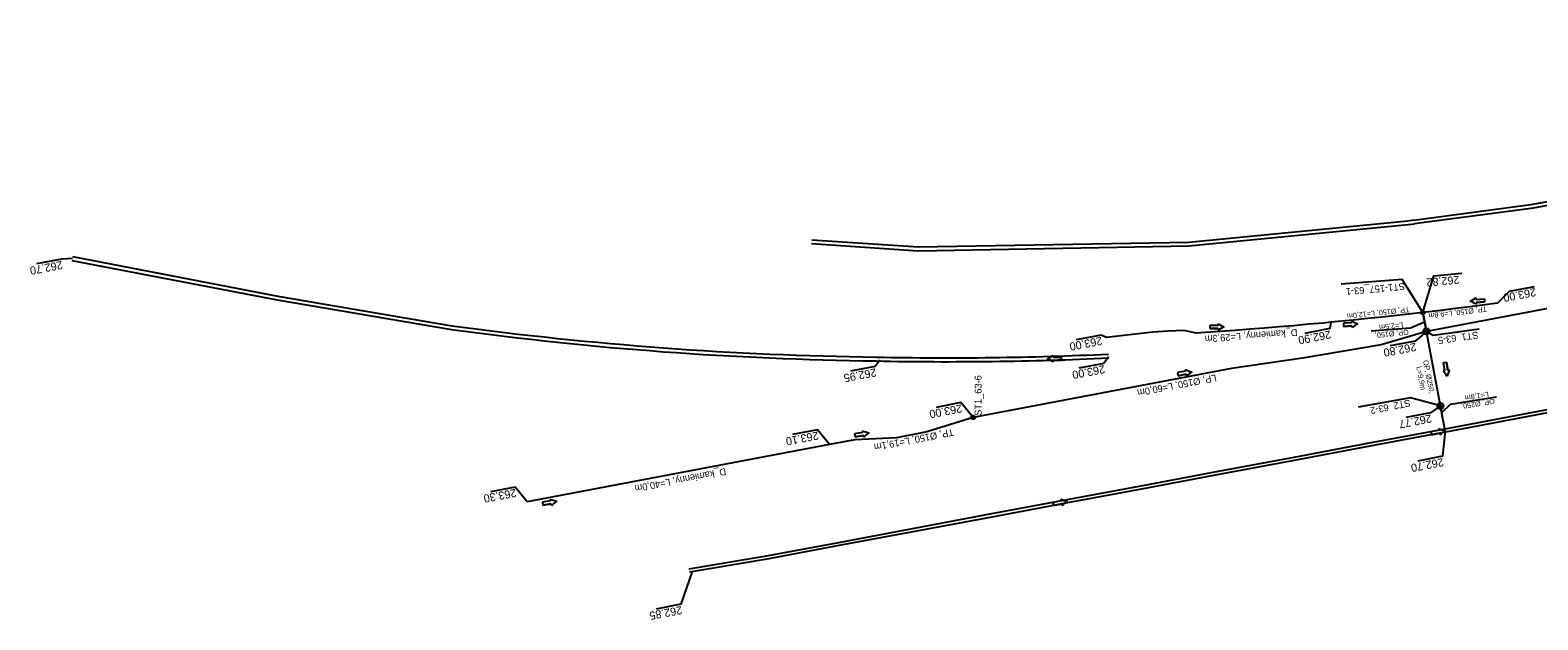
# Model space of a CAD drawing. Extents: x -1 to 65640748, y -22 to 5530284.
# Drawn here: x 6555645.9 to 6555842, y 5528336.8 to 5528413.6 of the extents above; entities that cross this region are included whole.
import ezdxf

# ---------------------------------------------------------------- set-up
doc = ezdxf.new("R2010")
doc.units = 0
for name, color, linetype in [('TOR_PROF-studnie i osadniki', 7, 'Continuous'), ('TOR_PS_ODW-drenaze', 7, 'Continuous'), ('TOR_PS_ODW-drenokolektory', 7, 'Continuous'), ('TOR_PS_ODW-kolektory', 7, 'Continuous'), ('TOR_PS_ODW-studnie PEHD', 7, 'Continuous'), ('TOR_PS_OPIS_O-opisy rurociagow', 7, 'Continuous'), ('TOR_PS_OPIS_O-opisy studni', 7, 'Continuous'), ('TOR_PS_OPIS_T-INFO', 7, 'Continuous'), ('TOR_PS_T-rowy otwarte nieumocnione', 7, 'Continuous'), ('TOR_PS_T-rowy otwarte umocnione', 7, 'Continuous')]:
    doc.layers.add(name, color=color, linetype=linetype)

msp = doc.modelspace()

# ---------------------------------------------------------------- linework, layer by layer
at = {"layer": 'TOR_PROF-studnie i osadniki'}
for centre, radius in [((6555827.04, 5528376.82), 0.25), ((6555827.04, 5528376.82), 0.125), ((6555768.56, 5528363.17), 0.25), ((6555768.56, 5528363.17), 0.125)]:
    msp.add_circle(centre, radius, dxfattribs=at)
at = {"layer": 'TOR_PS_ODW-drenaze'}
msp.add_line((6555749.88, 5528359.64), (6555710.58, 5528352.19), dxfattribs=at)
for points in [[(6555836.74, 5528378.02), (6555835.12, 5528377.8), (6555833.21, 5528377.56), (6555831.31, 5528377.33), (6555829.4, 5528377.09), (6555827.49, 5528376.87), (6555827.04, 5528376.82)], [(6555815.07, 5528375.54), (6555814.12, 5528375.45), (6555812.2, 5528375.28), (6555810.29, 5528375.1), (6555808.37, 5528374.94), (6555806.46, 5528374.78), (6555804.54, 5528374.63), (6555802.62, 5528374.49), (6555800.71, 5528374.35), (6555798.79, 5528374.22), (6555797.58, 5528374.15), (6555795.95, 5528374.49), (6555793.95, 5528374.39), (6555791.95, 5528374.28), (6555785.92, 5528373.56)], [(6555827.04, 5528376.82), (6555825.58, 5528376.65), (6555823.67, 5528376.43), (6555821.76, 5528376.23), (6555819.85, 5528376.02), (6555817.94, 5528375.83), (6555816.03, 5528375.64), (6555815.07, 5528375.54)], [(6555768.56, 5528363.17), (6555762.53, 5528361.27), (6555758.6, 5528360.52), (6555753.18, 5528360.26), (6555749.88, 5528359.64)]]:
    msp.add_lwpolyline(points, dxfattribs=at)
at = {"layer": 'TOR_PS_ODW-drenokolektory'}
for points in [[(6555871.72, 5528382.73), (6555827.51, 5528374.35), (6555827.51, 5528374.35)], [(6555827.51, 5528374.35), (6555821.64, 5528372.6), (6555811.41, 5528370.88), (6555802.18, 5528369.55), (6555768.56, 5528363.17)]]:
    msp.add_lwpolyline(points, dxfattribs=at)
at = {"layer": 'TOR_PS_ODW-kolektory'}
for points in [[(6555829.91, 5528361.65), (6555829.34, 5528364.67), (6555827.51, 5528374.35), (6555827.04, 5528376.82)], [(6555827.04, 5528376.82), (6555827.51, 5528374.35)], [(6555829.91, 5528361.65), (6555829.34, 5528364.67), (6555827.51, 5528374.35)], [(6555829.91, 5528361.65), (6555829.34, 5528364.67), (6555827.51, 5528374.35)], [(6555829.91, 5528361.65), (6555829.34, 5528364.67), (6555827.51, 5528374.35)], [(6555829.67, 5528362.94), (6555829.34, 5528364.67), (6555829.34, 5528364.67)]]:
    msp.add_lwpolyline(points, dxfattribs=at)
at = {"layer": 'TOR_PS_ODW-studnie PEHD'}
for centre, radius in [((6555827.04, 5528376.82), 0.25), ((6555827.04, 5528376.82), 0.112), ((6555827.51, 5528374.35), 0.4), ((6555827.51, 5528374.35), 0.145), ((6555829.34, 5528364.67), 0.4), ((6555829.34, 5528364.67), 0.145), ((6555768.56, 5528363.17), 0.25), ((6555768.56, 5528363.17), 0.112)]:
    msp.add_circle(centre, radius, dxfattribs=at)
at = {"layer": 'TOR_PS_OPIS_O-opisy rurociagow'}
for p, q in [((6555833.96, 5528378.52), (6555835.05, 5528378.6)), ((6555833.96, 5528378.52), (6555835.05, 5528378.6)), ((6555835.07, 5528378.2), (6555833.98, 5528378.12)), ((6555833.98, 5528378.12), (6555835.07, 5528378.2)), ((6555835.05, 5528378.6), (6555835.07, 5528378.2)), ((6555835.05, 5528378.6), (6555835.07, 5528378.2)), ((6555817.81, 5528375.49), (6555816.72, 5528375.41)), ((6555817.81, 5528375.49), (6555816.72, 5528375.41)), ((6555800.44, 5528375.14), (6555799.35, 5528375.12)), ((6555800.44, 5528375.14), (6555799.35, 5528375.12)), ((6555799.35, 5528375.12), (6555799.35, 5528374.72)), ((6555799.35, 5528375.12), (6555799.35, 5528374.72)), ((6555799.35, 5528374.72), (6555800.45, 5528374.74)), ((6555800.45, 5528374.74), (6555799.35, 5528374.72)), ((6555816.72, 5528375.41), (6555816.75, 5528375.01)), ((6555816.72, 5528375.41), (6555816.75, 5528375.01)), ((6555816.75, 5528375.01), (6555817.84, 5528375.09)), ((6555817.84, 5528375.09), (6555816.75, 5528375.01)), ((6555780.07, 5528371.02), (6555778.98, 5528371.01)), ((6555778.98, 5528371.01), (6555780.07, 5528371.02)), ((6555778.98, 5528370.61), (6555780.07, 5528370.62)), ((6555778.98, 5528370.61), (6555780.07, 5528370.62)), ((6555780.07, 5528370.62), (6555780.07, 5528371.02)), ((6555780.07, 5528370.62), (6555780.07, 5528371.02)), ((6555829.74, 5528370.32), (6555830.13, 5528370.37)), ((6555829.74, 5528370.32), (6555830.13, 5528370.37)), ((6555829.9, 5528369.24), (6555829.74, 5528370.32)), ((6555829.9, 5528369.24), (6555829.74, 5528370.32)), ((6555830.13, 5528370.37), (6555830.29, 5528369.29)), ((6555830.29, 5528369.29), (6555830.13, 5528370.37)), ((6555796.22, 5528369.17), (6555795.14, 5528368.99)), ((6555796.22, 5528369.17), (6555795.14, 5528368.99)), ((6555795.14, 5528368.99), (6555795.21, 5528368.59)), ((6555795.14, 5528368.99), (6555795.21, 5528368.59)), ((6555795.21, 5528368.59), (6555796.28, 5528368.78)), ((6555796.28, 5528368.78), (6555795.21, 5528368.59)), ((6555754.23, 5528361.21), (6555753.15, 5528361.03)), ((6555754.23, 5528361.21), (6555753.15, 5528361.03)), ((6555753.15, 5528361.03), (6555753.22, 5528360.63)), ((6555753.15, 5528361.03), (6555753.22, 5528360.63)), ((6555753.22, 5528360.63), (6555754.29, 5528360.82)), ((6555754.29, 5528360.82), (6555753.22, 5528360.63)), ((6555829.17, 5528361.51), (6555828.09, 5528361.31)), ((6555829.17, 5528361.51), (6555828.09, 5528361.31)), ((6555828.09, 5528361.31), (6555828.17, 5528360.91)), ((6555828.09, 5528361.31), (6555828.17, 5528360.91)), ((6555828.17, 5528360.91), (6555829.24, 5528361.12)), ((6555829.24, 5528361.12), (6555828.17, 5528360.91)), ((6555713.62, 5528352.32), (6555712.55, 5528352.14)), ((6555713.62, 5528352.32), (6555712.55, 5528352.14)), ((6555712.55, 5528352.14), (6555712.61, 5528351.74)), ((6555712.55, 5528352.14), (6555712.61, 5528351.74)), ((6555780.02, 5528352.3), (6555778.95, 5528352.1)), ((6555780.02, 5528352.3), (6555778.95, 5528352.1)), ((6555778.95, 5528352.1), (6555779.02, 5528351.71)), ((6555778.95, 5528352.1), (6555779.02, 5528351.71)), ((6555712.61, 5528351.74), (6555713.69, 5528351.93)), ((6555713.69, 5528351.93), (6555712.61, 5528351.74)), ((6555779.02, 5528351.71), (6555780.1, 5528351.91)), ((6555780.1, 5528351.91), (6555779.02, 5528351.71))]:
    msp.add_line(p, q, dxfattribs=at)
for points in [[(6555833.95, 5528378.75), (6555833.95, 5528378.75)], [(6555834.01, 5528377.9), (6555834.01, 5528377.9)], [(6555817.78, 5528375.72), (6555817.78, 5528375.72)], [(6555800.42, 5528375.37), (6555800.42, 5528375.37)], [(6555800.44, 5528374.52), (6555800.44, 5528374.52)], [(6555817.85, 5528374.87), (6555817.85, 5528374.87)], [(6555778.98, 5528371.23), (6555778.98, 5528371.23)], [(6555778.99, 5528370.38), (6555778.99, 5528370.38)], [(6555796.17, 5528369.39), (6555796.17, 5528369.39)], [(6555796.31, 5528368.56), (6555796.31, 5528368.56)], [(6555829.67, 5528369.21), (6555829.67, 5528369.21)], [(6555830.51, 5528369.34), (6555830.51, 5528369.34)], [(6555754.18, 5528361.43), (6555754.18, 5528361.43)], [(6555754.32, 5528360.6), (6555754.32, 5528360.6)], [(6555829.12, 5528361.73), (6555829.12, 5528361.73)], [(6555829.27, 5528360.89), (6555829.27, 5528360.89)], [(6555713.57, 5528352.54), (6555713.57, 5528352.54)], [(6555779.97, 5528352.52), (6555779.97, 5528352.52)], [(6555713.72, 5528351.71), (6555713.72, 5528351.71)], [(6555780.13, 5528351.68), (6555780.13, 5528351.68)]]:
    msp.add_lwpolyline(points, dxfattribs=at)
for centre, radius, start, end in [((6555830.95, 5528382.64), 4.92, 297.3085, 307.6904), ((6555830.95, 5528382.64), 4.92, 297.3085, 307.6904), ((6555831.57, 5528373.63), 4.92, 60.2707, 70.6525), ((6555831.57, 5528373.63), 4.92, 60.2707, 70.6525), ((6555833.51, 5528378.62), 0.458, 347.1146, 15.5758), ((6555833.51, 5528378.62), 0.458, 347.1146, 15.5758), ((6555833.56, 5528377.96), 0.458, 352.3852, 20.8465), ((6555833.56, 5528377.96), 0.458, 352.3852, 20.8465), ((6555820.2, 5528380), 4.92, 240.5204, 250.9022), ((6555818.24, 5528375.66), 0.458, 172.635, 201.0962), ((6555820.2, 5528380), 4.92, 240.5204, 250.9022), ((6555818.24, 5528375.66), 0.458, 172.635, 201.0962), ((6555800.87, 5528375.29), 0.458, 169.7553, 198.2165), ((6555800.87, 5528375.29), 0.458, 169.7553, 198.2165), ((6555803.05, 5528379.52), 4.92, 237.6407, 248.0225), ((6555803.05, 5528379.52), 4.92, 237.6407, 248.0225), ((6555800.89, 5528374.62), 0.458, 164.4846, 192.9458), ((6555800.89, 5528374.62), 0.458, 164.4846, 192.9458), ((6555803.27, 5528370.49), 4.92, 114.6786, 125.0604), ((6555803.27, 5528370.49), 4.92, 114.6786, 125.0604), ((6555818.29, 5528374.99), 0.458, 167.3643, 195.8256), ((6555818.29, 5528374.99), 0.458, 167.3643, 195.8256), ((6555820.87, 5528370.99), 4.92, 117.5583, 127.9401), ((6555820.87, 5528370.99), 4.92, 117.5583, 127.9401), ((6555776.21, 5528375.29), 4.92, 293.986, 304.3678), ((6555776.21, 5528375.29), 4.92, 293.986, 304.3678), ((6555776.31, 5528366.26), 4.92, 56.9481, 67.3299), ((6555776.31, 5528366.26), 4.92, 56.9481, 67.3299), ((6555778.54, 5528371.14), 0.458, 343.792, 12.2532), ((6555778.54, 5528371.14), 0.458, 343.792, 12.2532), ((6555778.55, 5528370.47), 0.458, 349.0626, 17.5239), ((6555778.55, 5528370.47), 0.458, 349.0626, 17.5239), ((6555798.16, 5528373.89), 4.92, 246.1449, 256.5268), ((6555796.62, 5528369.38), 0.458, 178.2595, 206.7208), ((6555798.16, 5528373.89), 4.92, 246.1449, 256.5268), ((6555796.62, 5528369.38), 0.458, 178.2595, 206.7208), ((6555796.74, 5528368.72), 0.458, 172.9889, 201.4501), ((6555796.74, 5528368.72), 0.458, 172.9889, 201.4501), ((6555799.7, 5528364.99), 4.92, 123.1828, 133.5647), ((6555799.7, 5528364.99), 4.92, 123.1828, 133.5647), ((6555829.83, 5528368.78), 0.458, 81.4934, 109.9546), ((6555829.83, 5528368.78), 0.458, 81.4934, 109.9546), ((6555826.02, 5528365.92), 4.92, 31.6874, 42.0692), ((6555826.02, 5528365.92), 4.92, 31.6874, 42.0692), ((6555834.96, 5528367.23), 4.92, 154.6495, 165.0313), ((6555834.96, 5528367.23), 4.92, 154.6495, 165.0313), ((6555830.49, 5528368.88), 0.458, 86.764, 115.2253), ((6555830.49, 5528368.88), 0.458, 86.764, 115.2253), ((6555756.17, 5528365.93), 4.92, 246.1449, 256.5268), ((6555754.63, 5528361.42), 0.458, 178.2595, 206.7208), ((6555756.17, 5528365.93), 4.92, 246.1449, 256.5268), ((6555754.63, 5528361.42), 0.458, 178.2595, 206.7208), ((6555754.75, 5528360.76), 0.458, 172.9889, 201.4501), ((6555754.75, 5528360.76), 0.458, 172.9889, 201.4501), ((6555757.71, 5528357.03), 4.92, 123.1828, 133.5647), ((6555757.71, 5528357.03), 4.92, 123.1828, 133.5647), ((6555831.04, 5528366.25), 4.92, 246.9461, 257.3279), ((6555829.57, 5528361.72), 0.458, 179.0606, 207.5219), ((6555831.04, 5528366.25), 4.92, 246.9461, 257.3279), ((6555829.57, 5528361.72), 0.458, 179.0606, 207.5219), ((6555829.7, 5528361.07), 0.458, 173.79, 202.2512), ((6555829.7, 5528361.07), 0.458, 173.79, 202.2512), ((6555832.71, 5528357.38), 4.92, 123.9839, 134.3658), ((6555832.71, 5528357.38), 4.92, 123.9839, 134.3658), ((6555715.56, 5528357.04), 4.92, 246.1449, 256.5268), ((6555714.03, 5528352.53), 0.458, 178.2595, 206.7208), ((6555715.56, 5528357.04), 4.92, 246.1449, 256.5268), ((6555714.03, 5528352.53), 0.458, 178.2595, 206.7208), ((6555717.11, 5528348.14), 4.92, 123.1828, 133.5647), ((6555717.11, 5528348.14), 4.92, 123.1828, 133.5647), ((6555781.9, 5528357.04), 4.92, 246.9045, 257.2864), ((6555780.43, 5528352.51), 0.458, 179.0191, 207.4803), ((6555781.9, 5528357.04), 4.92, 246.9045, 257.2864), ((6555780.43, 5528352.51), 0.458, 179.0191, 207.4803), ((6555783.57, 5528348.17), 4.92, 123.9424, 134.3242), ((6555783.57, 5528348.17), 4.92, 123.9424, 134.3242), ((6555714.14, 5528351.87), 0.458, 172.9889, 201.4501), ((6555714.14, 5528351.87), 0.458, 172.9889, 201.4501), ((6555780.55, 5528351.86), 0.458, 173.7484, 202.2097), ((6555780.55, 5528351.86), 0.458, 173.7484, 202.2097)]:
    msp.add_arc(centre, radius, start, end, dxfattribs=at)
at = {"layer": 'TOR_PS_OPIS_T-INFO'}
for points in [[(6555651.43, 5528383.83), (6555650, 5528383.76), (6555646.77, 5528383.14)], [(6555827.04, 5528376.82), (6555828.49, 5528381.57), (6555832.14, 5528381.93)], [(6555827.04, 5528376.82), (6555824.38, 5528381.1), (6555816.44, 5528380.49)], [(6555836.74, 5528378.02), (6555838.32, 5528379.61), (6555841.56, 5528380.21)], [(6555815.07, 5528375.54), (6555814.95, 5528374.72), (6555811.72, 5528374.09)], [(6555827.27, 5528375.58), (6555825.43, 5528374.79), (6555820.31, 5528374.39)], [(6555785.92, 5528373.56), (6555785.21, 5528373.89), (6555781.97, 5528373.26)], [(6555827.51, 5528374.35), (6555826.04, 5528373.1), (6555822.81, 5528372.48)], [(6555827.51, 5528374.35), (6555828.41, 5528373.85), (6555834.39, 5528374.7)], [(6555756.43, 5528370.62), (6555755.83, 5528369.79), (6555752.6, 5528369.17)], [(6555786.16, 5528371.03), (6555785.56, 5528370.2), (6555782.32, 5528369.58)], [(6555829.34, 5528364.67), (6555825.44, 5528365.7), (6555818.64, 5528364.49)], [(6555829.5, 5528363.8), (6555830.66, 5528364.91), (6555836.63, 5528365.86)], [(6555768.56, 5528363.17), (6555766.98, 5528365.09), (6555763.75, 5528364.47)], [(6555829.34, 5528364.67), (6555828.05, 5528363.78), (6555824.82, 5528363.16)], [(6555749.88, 5528359.64), (6555748.31, 5528361.55), (6555745.08, 5528360.93)], [(6555829.96, 5528361.46), (6555829.61, 5528358.11), (6555826.38, 5528357.48)], [(6555710.58, 5528352.19), (6555709.01, 5528354.1), (6555705.78, 5528353.48)], [(6555732.01, 5528343.1), (6555730.57, 5528338.86), (6555727.33, 5528338.23)]]:
    msp.add_lwpolyline(points, dxfattribs=at)
at = {"layer": 'TOR_PS_T-rowy otwarte nieumocnione'}
for points in [[(6555825.88, 5528388.85), (6555841.38, 5528390.92), (6555883.85, 5528398.71), (6555924.19, 5528406.04), (6555964.88, 5528413.56)], [(6555825.94, 5528388.38), (6555841.45, 5528390.45), (6555883.94, 5528398.24), (6555924.27, 5528405.57), (6555964.49, 5528413.01), (6555964.97, 5528413.1)], [(6555761.43, 5528385.35), (6555796.6, 5528385.99), (6555825.1, 5528388.76), (6555825.88, 5528388.86)], [(6555761.44, 5528384.85), (6555796.63, 5528385.49), (6555825.15, 5528388.26), (6555825.95, 5528388.37)], [(6555747.55, 5528385.79), (6555761.42, 5528384.85)], [(6555747.57, 5528386.29), (6555761.46, 5528385.35)]]:
    msp.add_lwpolyline(points, dxfattribs=at)
at = {"layer": 'TOR_PS_T-rowy otwarte umocnione'}
for points in [[(6556006.81, 5528394.95), (6555996.98, 5528393.09), (6555987.15, 5528391.24), (6555977.33, 5528389.39), (6555971.28, 5528388.25), (6555971.27, 5528388.25), (6555967.5, 5528387.54), (6555957.67, 5528385.69), (6555947.84, 5528383.84), (6555938.02, 5528381.99), (6555928.19, 5528380.14), (6555918.36, 5528378.29), (6555908.53, 5528376.44), (6555898.71, 5528374.6), (6555888.88, 5528372.75), (6555879.05, 5528370.9), (6555869.22, 5528369.05), (6555859.4, 5528367.2), (6555849.57, 5528365.35), (6555839.74, 5528363.5), (6555829.91, 5528361.65)], [(6555651.35, 5528383.6), (6555678.06, 5528378.46), (6555700.72, 5528374.6), (6555700.72, 5528374.6)], [(6555651.45, 5528384.09), (6555678.15, 5528378.95), (6555700.78, 5528375.1)], [(6555849.64, 5528364.96), (6555839.82, 5528363.11), (6555829.99, 5528361.26), (6555829.89, 5528361.24), (6555820.16, 5528359.41), (6555810.33, 5528357.57), (6555800.5, 5528355.73), (6555790.67, 5528353.89), (6555780.84, 5528352.05), (6555771.01, 5528350.2), (6555761.19, 5528348.36), (6555751.36, 5528346.52), (6555741.53, 5528344.68), (6555731.66, 5528343.02)], [(6555829.91, 5528361.65), (6555820.08, 5528359.81), (6555810.26, 5528357.97), (6555800.43, 5528356.12), (6555790.6, 5528354.28), (6555780.77, 5528352.44), (6555770.94, 5528350.6), (6555761.11, 5528348.76), (6555751.28, 5528346.91), (6555741.45, 5528345.07), (6555731.59, 5528343.41)]]:
    msp.add_lwpolyline(points, dxfattribs=at)
for centre, radius, start, end in [((6555761.89, 5528825.98), 455.5, 262.2824, 269.2524), ((6555761.89, 5528825.98), 455, 262.2824, 269.2526), ((6555765.13, 5528825.67), 455.25, 268.8438, 272.6523), ((6555765.13, 5528825.67), 454.75, 268.8436, 272.6518)]:
    msp.add_arc(centre, radius, start, end, dxfattribs=at)

# ---------------------------------------------------------------- texts
at = {"layer": 'TOR_PS_OPIS_O-opisy rurociagow'}
for s, height, rotation, p in [('TP, Ø150, L=12,0m', 0.675, 186.026, (6555825.26, 5528377.54)), ('TP, Ø150, L=9,8m', 0.675, 186.6066, (6555835.34, 5528377.6)), ('L=2,5m', 0.675, 185.5769, (6555824.45, 5528375.54)), ('D_kamienny, L=29,3m', 0.9, 184.0641, (6555810.71, 5528374.67)), ('OP, Ø150, ', 0.675, 185.5769, (6555825.18, 5528374.6)), ('L=9,9m', 0.675, 280.821, (6555826.2, 5528369.76)), ('OP, Ø250, ', 0.675, 280.821, (6555827.08, 5528370.56)), ('LP, Ø150, L=60,0m', 0.9, 190.9157, (6555800.12, 5528368.77)), ('L=1,8m', 0.675, 189.125, (6555835.56, 5528366.52)), ('OP, Ø250, ', 0.675, 189.125, (6555836.34, 5528365.62)), ('TP, Ø150, L=19,1m', 0.9, 190.9157, (6555765.95, 5528361.69)), ('D_kamienny, L=40,0m', 0.9, 190.7332, (6555736.34, 5528356.58))]:
    msp.add_text(s, height=height, rotation=rotation, dxfattribs=at).set_placement(p)
at = {"layer": 'TOR_PS_OPIS_O-opisy studni'}
for s, rotation, p in [('ST1-157_63-1', 185.3952, (6555824.67, 5528380.68)), ('ST1_63-5', 188.0687, (6555834.2, 5528374.35)), ('ST1_63-6', 90, (6555769.66, 5528363.37)), ('ST2_63-2', 191.335, (6555825.33, 5528365.5))]:
    msp.add_text(s, height=0.9, rotation=rotation, dxfattribs=at).set_placement(p)
at = {"layer": 'TOR_PS_OPIS_T-INFO'}
for s, rotation, p in [('262.70', 190.7159, (6555650.04, 5528383.54)), ('262.82', 184.7849, (6555831.76, 5528381.6)), ('263.00', 190.7506, (6555841.66, 5528380.01)), ('263.00', 190.7159, (6555785.25, 5528373.66)), ('262.90', 190.7159, (6555814.99, 5528374.49)), ('262.80', 190.7159, (6555826.08, 5528372.87)), ('263.00', 190.7159, (6555785.6, 5528369.98)), ('262.95', 190.7159, (6555755.88, 5528369.56)), ('263.00', 190.7159, (6555767.02, 5528364.87)), ('262.77', 190.7159, (6555828.09, 5528363.56)), ('263.10', 190.7159, (6555748.35, 5528361.33)), ('262.70', 190.7159, (6555829.65, 5528357.88)), ('263.30', 190.7159, (6555709.05, 5528353.88)), ('262.85', 190.7159, (6555730.61, 5528338.63))]:
    msp.add_text(s, height=1.05, rotation=rotation, dxfattribs=at).set_placement(p)

doc.saveas('drawing.dxf')
